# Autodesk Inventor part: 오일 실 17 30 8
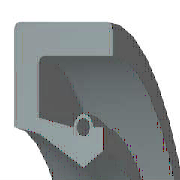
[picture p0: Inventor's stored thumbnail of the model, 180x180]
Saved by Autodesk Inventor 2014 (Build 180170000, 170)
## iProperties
IsCustomPart: 1
Created: 2012-02
Part Number: 오일 실 17 30 8
Material: 고무
Description: 오일-실
Document SubType Name: Modeling
Standard: KS B 2804
Designer: test
Standards Organization: KS
Language: ko-KR
Size Designation: S - 17 32 8
Categories: <MemberInstance><Categories><Category DisplayName="샤프트 부품" InternalName="7f7aeb1f-a693-4053-b835-cee3144e0d98" Mnemonic="SHFT"><Category DisplayName="실링" Intern
Density: 0.93 g/cm^3
Mass: 1.6913 g
Surface Area: 28.0102 cm^2
Volume: 1.81861 cm^3
Appearance: 고무 - 검은색 - 버전 1.1
Author: test
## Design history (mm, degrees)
revolve "본체" stored, may be unused: angle "d17" = 90 deg
revolve "스프링1" stored, may be unused: angle "d18" = 90 deg
body "Solid1"
sketch "스케치1"
  geometry: L1 (0, 15)-(8, 15); L2 (8, 15)-(8, 13.75); L3 (8, 13.75)-(1.75, 13.75); L4 (0, 15)-(0, 10.6); L5 (0, 10.6)-(1.75, 10.25); L6 (1.75, 10.25)-(4.9, 8.5); L7 (4.9, 8.5)-(0, 8.5); L8 (6.3, 9.375)-(6.3, 10.6); L9 (0, 0)-(9.586, 0) reference; L10 (4.9, 8.5)-(6.3, 9.375); L11 (0, 19.2)-(0, -3.2) reference; L12 (-1.917, 0)-(11.503, 0) reference; L13 (4.2, 10.6)-(1.75, 11.09); L14 (1.75, 11.09)-(1.75, 13.75); L15 (6.3, 10.6)-(5.6, 10.6); C1 r 0.455 at (4.9, 10.6); A1 r 0.7 centre (4.9, 10.6) between (5.6, 10.6) and (4.2, 10.6)
  constraints: 26 end point, 5 horizontal alignment, 4 perpendicular, 2 centre point, 2 collinear, 2 horizontal, 2 parallel, 2 point on circle, 2 point on line, 2 vertical alignment, 1 coincident
  dimensions: "d0" = 30 diameter of L1 L9 (= SD2); "d1" = 18.75 diameter of L8.start L9 (= ABDM); "d2" = 1.25 distance of L1.end L2.end (computed from SD); "d3" = 0.91 diameter of C1 (= SPDI); "d4" = 1.4 diameter of A1 (= SPDA); "d5" = 17 diameter of L6.end L9 (= NND); "d6" = 20.5 diameter of L5.end L9 (= TKDM); "d7" = 21.2 diameter of L4.end L9 (= HLDM); "d8" = 4.9 distance from line of C1.centre L4 (= SPDST); "d9" = 6.3 distance between parallel lines of L8 L4 (= SDI); "d10" = 8 distance between parallel lines of L2 L4 (= SWDT); "d12" = 1.75 distance between parallel lines of L14 L4 (= SD)
fillet "모깎기1" dims "d11" = 0.3 (= RR)
other parameters: "SD2" = 30 [user parameter; used in 1 equation term], "SWDT" = 8 [user parameter; used in 1 equation term], "RR" = 0.3 [user parameter; used in 1 equation term], "SD" = 1.75 [user parameter; used in 2 equation terms], "NND" = 17 [user parameter; used in 1 equation term], "SPDA" = 1.4 [user parameter; used in 1 equation term], "SPDI" = 0.91 [user parameter; used in 1 equation term], "TKDM" = 20.5 [user parameter; used in 1 equation term], "HLDM" = 21.2 [user parameter; used in 1 equation term], "ABDM" = 18.75 [user parameter; used in 1 equation term], "SDI" = 6.3 [user parameter; used in 1 equation term], "SPDST" = 4.9 [user parameter; used in 1 equation term], "d13" = 0, "d14" = 0, "d15" = 0, "LAB" = 0.35 [user parameter]
